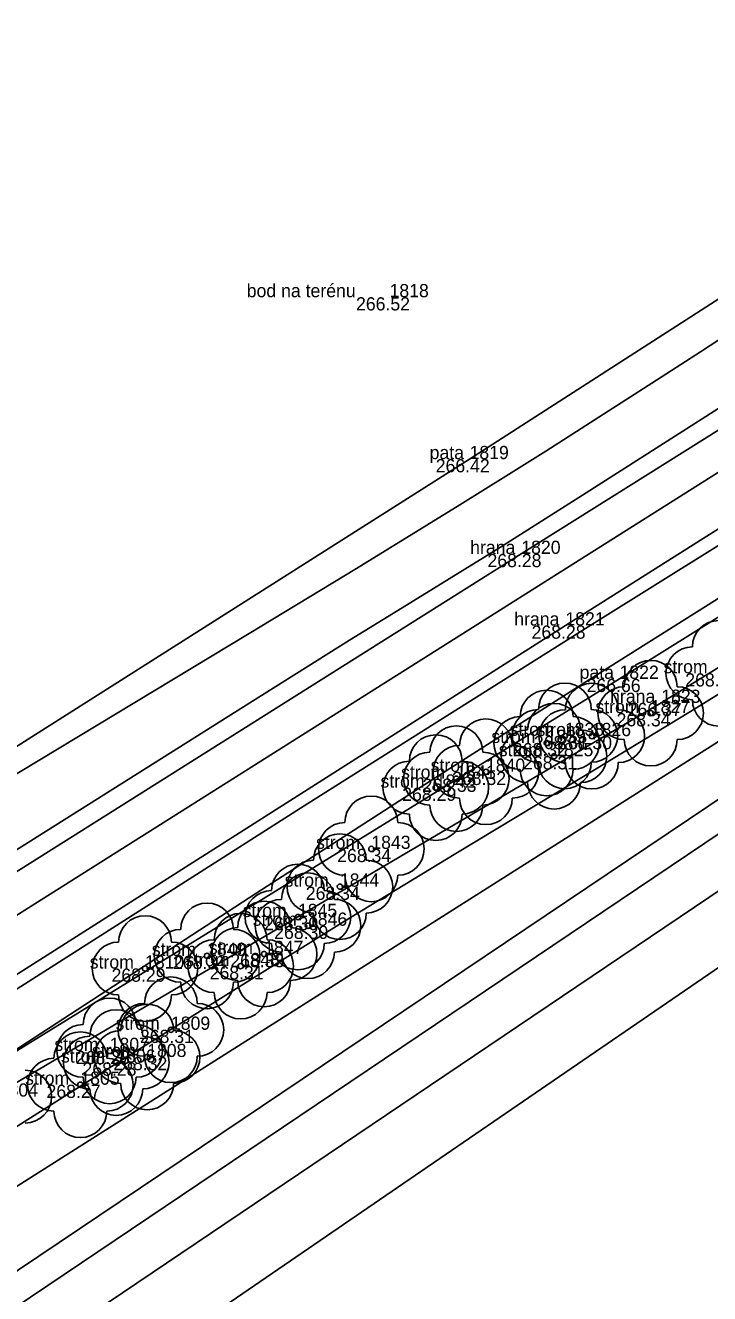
# Model space of a CAD drawing. Extents: x -567962 to -566460, y -1093720 to -1089838.
# Drawn here: x -566832.41 to -566806.5, y -1090168.25 to -1090120.23 of the extents above; entities that cross this region are included whole.
import ezdxf

# ---------------------------------------------------------------- set-up
doc = ezdxf.new("R2010")
doc.units = 0
for name, color, linetype in [('0_osa hráze', 7, 'Continuous'), ('bod_znacka', 7, 'Continuous'), ('cislo_bodu', 7, 'Continuous'), ('Doměření - kraj pole', 7, 'Continuous'), ('hrana_L', 7, 'Continuous'), ('hrana_P', 7, 'Continuous'), ('kod_bodu', 7, 'Continuous'), ('norm_vrst', 7, 'Continuous'), ('stromy', 7, 'Continuous'), ('vyska_bodu', 7, 'Continuous')]:
    doc.layers.add(name, color=color, linetype=linetype)

msp = doc.modelspace()

# ---------------------------------------------------------------- linework, layer by layer
at = {"layer": '0_osa hráze'}
msp.add_lwpolyline([(-566672.431, -1090052.714), (-566840.66, -1090158.92), (-566848.661, -1090164.285)], dxfattribs=at)
at = {"layer": 'bod_znacka'}
for p, q in [((-566818.62, -1090130.52), (-566818.62, -1090130.52)), ((-566815.59, -1090136.65), (-566815.59, -1090136.65)), ((-566813.63, -1090140.24), (-566813.63, -1090140.24)), ((-566811.96, -1090142.95), (-566811.96, -1090142.95)), ((-566809.91, -1090144.97), (-566809.91, -1090144.97)), ((-566808.33, -1090145.88), (-566808.33, -1090145.88)), ((-566808.73, -1090146.27), (-566808.73, -1090146.27)), ((-566812.67, -1090147.4), (-566812.67, -1090147.4)), ((-566811.98, -1090147.13), (-566811.98, -1090147.13)), ((-566810.96, -1090147.14), (-566810.96, -1090147.14)), ((-566812.39, -1090147.9), (-566812.39, -1090147.9)), ((-566816.09, -1090148.75), (-566816.09, -1090148.75)), ((-566814.97, -1090148.49), (-566814.97, -1090148.49)), ((-566816.87, -1090149.09), (-566816.87, -1090149.09)), ((-566819.31, -1090151.41), (-566819.31, -1090151.41)), ((-566820.5, -1090152.84), (-566820.5, -1090152.84)), ((-566822.09, -1090153.99), (-566822.09, -1090153.99)), ((-566821.71, -1090154.32), (-566821.71, -1090154.32)), ((-566825.53, -1090155.46), (-566825.53, -1090155.46)), ((-566823.37, -1090155.39), (-566823.37, -1090155.39)), ((-566827.88, -1090155.94), (-566827.88, -1090155.94)), ((-566824.26, -1090155.85), (-566824.26, -1090155.85)), ((-566826.9, -1090158.26), (-566826.9, -1090158.26)), ((-566829.22, -1090159.06), (-566829.22, -1090159.06)), ((-566827.8, -1090159.29), (-566827.8, -1090159.29)), ((-566828.97, -1090159.5), (-566828.97, -1090159.5)), ((-566830.33, -1090160.34), (-566830.33, -1090160.34))]:
    msp.add_line(p, q, dxfattribs=at)
at = {"layer": 'Doměření - kraj pole'}
msp.add_lwpolyline([(-567047.906, -1090663.012), (-567047.627, -1090662.294), (-567014.86, -1090563.09), (-567002.362, -1090535.532), (-566955.49, -1090317.15), (-566941.63, -1090287.13), (-566940.57, -1090285.53), (-566924.46, -1090259.19), (-566900.35, -1090228.87), (-566877.72, -1090206.37), (-566851.19, -1090186.75), (-566766.44, -1090128.68), (-566717.21, -1090096.34), (-566711.98, -1090092.48)], dxfattribs=at)
at = {"layer": 'hrana_L'}
for p, q in [((-566791.87, -1090121.39), (-566815.59, -1090136.65)), ((-566789.46, -1090125.04), (-566813.63, -1090140.24)), ((-566811.96, -1090142.95), (-566787.81, -1090127.7)), ((-566809.91, -1090144.97), (-566786.12, -1090130.08)), ((-566784.05, -1090130.81), (-566808.33, -1090145.88)), ((-566815.59, -1090136.65), (-566844.61, -1090155.03)), ((-566813.63, -1090140.24), (-566842.64, -1090158.49)), ((-566811.96, -1090142.95), (-566840.71, -1090161.23)), ((-566839.34, -1090163.12), (-566809.91, -1090144.97)), ((-566808.33, -1090145.88), (-566838.78, -1090163.8))]:
    msp.add_line(p, q, dxfattribs=at)
for points in [[(-567053.87, -1090661.84), (-567020.06, -1090563.34), (-567005.258, -1090534.966), (-566958.763, -1090315.674), (-566944.67, -1090284.66), (-566926.49, -1090256.26), (-566902.65, -1090226.03), (-566881.28, -1090203.14), (-566853.44, -1090182.668), (-566715.257, -1090089.634)], [(-567050.54, -1090661.95), (-567017.83, -1090562.99), (-567002.61, -1090535.52), (-566957.72, -1090316.45), (-566942.31, -1090285.07), (-566925.11, -1090257.71), (-566901.37, -1090227.4), (-566879.5, -1090205.23), (-566852.16, -1090184), (-566767.57, -1090126.99), (-566713.28, -1090090.76)], [(-566881.23, -1090201.89), (-566854.215, -1090181.819), (-566730.44, -1090098.63)]]:
    msp.add_lwpolyline(points, dxfattribs=at)
at = {"layer": 'hrana_P'}
msp.add_line((-566838.46, -1090167.8), (-566805.13, -1090146.69), dxfattribs=at)
at = {"layer": 'norm_vrst'}
for points in [[(-566834.345, -1090157.735), (-566821.711, -1090149.692), (-566816.354, -1090146.304), (-566810.753, -1090142.78), (-566801.92, -1090137.275), (-566787.313, -1090128.226), (-566770.443, -1090117.747), (-566767.019, -1090115.602), (-566760.086, -1090111.215), (-566758.405, -1090110.141), (-566751.751, -1090105.855), (-566741.749, -1090099.395), (-566740.082, -1090098.328), (-566733.458, -1090094.138), (-566723.987, -1090088.226), (-566707.595, -1090078.051)], [(-566722.704, -1090081.135), (-566724.539, -1090082.312), (-566725.783, -1090083.096), (-566732.745, -1090087.421), (-566735.695, -1090089.236), (-566737.009, -1090090.068), (-566753.591, -1090100.68), (-566755.229, -1090101.72), (-566761.398, -1090105.6), (-566763.069, -1090106.675), (-566771.123, -1090111.96), (-566784.371, -1090120.618), (-566793.768, -1090126.774), (-566795.254, -1090127.74), (-566801.058, -1090131.472), (-566811.306, -1090138.019), (-566814.423, -1090139.986), (-566818.311, -1090142.378), (-566820.132, -1090143.508), (-566823.816, -1090145.814), (-566841.877, -1090157.194)], [(-566834.812, -1090160.328), (-566823.649, -1090153.068), (-566816.894, -1090148.721), (-566811.051, -1090145.001), (-566804.846, -1090141.096), (-566798.967, -1090137.445), (-566785.889, -1090129.374), (-566780.734, -1090126.153), (-566758.401, -1090112.077), (-566740.288, -1090100.594), (-566732.104, -1090095.458), (-566727.633, -1090092.705), (-566722.521, -1090089.608)], [(-566783.674, -1090117.162), (-566791.52, -1090122.368), (-566799.806, -1090127.931), (-566803.955, -1090130.69), (-566806.841, -1090132.583), (-566808.328, -1090133.547), (-566812.705, -1090136.343), (-566814.213, -1090137.296), (-566815.954, -1090138.383), (-566819.876, -1090140.794), (-566823.933, -1090143.254), (-566834.017, -1090149.319)], [(-566833.079, -1090162.132), (-566828.853, -1090159.464), (-566824.724, -1090156.881), (-566820.322, -1090154.152), (-566816.111, -1090151.584), (-566810.797, -1090148.383), (-566807, -1090146.064), (-566793.395, -1090137.626), (-566790.657, -1090135.906), (-566782.34, -1090130.593), (-566769.314, -1090122.25)]]:
    msp.add_lwpolyline(points, dxfattribs=at)
at = {"layer": 'stromy'}
for centre in [(-566808.73, -1090146.27), (-566812.67, -1090147.4), (-566811.98, -1090147.13), (-566810.96, -1090147.14), (-566812.39, -1090147.9), (-566814.97, -1090148.49), (-566816.09, -1090148.75), (-566816.87, -1090149.09), (-566819.31, -1090151.41), (-566820.5, -1090152.84), (-566822.09, -1090153.99), (-566821.71, -1090154.32), (-566825.53, -1090155.46), (-566823.37, -1090155.39), (-566827.88, -1090155.94), (-566824.26, -1090155.85), (-566826.9, -1090158.26), (-566829.22, -1090159.06), (-566828.97, -1090159.5), (-566827.8, -1090159.29), (-566830.33, -1090160.34)]:
    msp.add_circle(centre, 0.1, dxfattribs=at)
for centre, start, end in [((-566806.15, -1090143.76), 0, 180), ((-566807.15, -1090144.76), 90, 270), ((-566808.73, -1090145.27), 0, 180), ((-566812.67, -1090146.4), 0, 180), ((-566811.98, -1090146.13), 0, 180), ((-566810.96, -1090146.14), 0, 180), ((-566809.73, -1090146.27), 90, 270), ((-566807.73, -1090146.27), 270, 90), ((-566812.39, -1090146.9), 0, 180), ((-566806.15, -1090145.76), 180, 0), ((-566813.67, -1090147.4), 90, 270), ((-566812.98, -1090147.13), 90, 270), ((-566811.96, -1090147.14), 90, 270), ((-566811.67, -1090147.4), 270, 90), ((-566810.98, -1090147.13), 270, 90), ((-566809.96, -1090147.14), 270, 90), ((-566816.09, -1090147.75), 0, 180), ((-566814.97, -1090147.49), 0, 180), ((-566813.39, -1090147.9), 90, 270), ((-566811.39, -1090147.9), 270, 90), ((-566816.87, -1090148.09), 0, 180), ((-566808.73, -1090147.27), 180, 0), ((-566817.09, -1090148.75), 90, 270), ((-566815.97, -1090148.49), 90, 270), ((-566815.09, -1090148.75), 270, 90), ((-566813.97, -1090148.49), 270, 90), ((-566817.87, -1090149.09), 90, 270), ((-566815.87, -1090149.09), 270, 90), ((-566811.98, -1090148.13), 180, 0), ((-566810.96, -1090148.14), 180, 0), ((-566812.67, -1090148.4), 180, 0), ((-566812.39, -1090148.9), 180, 0), ((-566819.31, -1090150.41), 0, 180), ((-566816.09, -1090149.75), 180, 0), ((-566814.97, -1090149.49), 180, 0), ((-566816.87, -1090150.09), 180, 0), ((-566820.31, -1090151.41), 90, 270), ((-566818.31, -1090151.41), 270, 90), ((-566820.5, -1090151.84), 0, 180), ((-566822.09, -1090152.99), 0, 180), ((-566821.5, -1090152.84), 90, 270), ((-566819.5, -1090152.84), 270, 90), ((-566821.71, -1090153.32), 0, 180), ((-566819.31, -1090152.41), 180, 0), ((-566823.09, -1090153.99), 90, 270), ((-566821.09, -1090153.99), 270, 90), ((-566825.53, -1090154.46), 0, 180), ((-566823.37, -1090154.39), 0, 180), ((-566822.71, -1090154.32), 90, 270), ((-566820.71, -1090154.32), 270, 90), ((-566827.88, -1090154.94), 0, 180), ((-566824.26, -1090154.85), 0, 180), ((-566820.5, -1090153.84), 180, 0), ((-566826.53, -1090155.46), 90, 270), ((-566824.37, -1090155.39), 90, 270), ((-566824.53, -1090155.46), 270, 90), ((-566822.37, -1090155.39), 270, 90), ((-566828.88, -1090155.94), 90, 270), ((-566826.88, -1090155.94), 270, 90), ((-566825.26, -1090155.85), 90, 270), ((-566823.26, -1090155.85), 270, 90), ((-566822.09, -1090154.99), 180, 0), ((-566821.71, -1090155.32), 180, 0), ((-566826.9, -1090157.26), 0, 180), ((-566825.53, -1090156.46), 180, 0), ((-566823.37, -1090156.39), 180, 0), ((-566827.88, -1090156.94), 180, 0), ((-566824.26, -1090156.85), 180, 0), ((-566829.22, -1090158.06), 0, 180), ((-566828.97, -1090158.5), 0, 180), ((-566827.9, -1090158.26), 90, 270), ((-566827.8, -1090158.29), 0, 180), ((-566825.9, -1090158.26), 270, 90), ((-566830.33, -1090159.34), 0, 180), ((-566830.22, -1090159.06), 90, 270), ((-566828.8, -1090159.29), 90, 270), ((-566828.22, -1090159.06), 270, 90), ((-566826.8, -1090159.29), 270, 90), ((-566829.97, -1090159.5), 90, 270), ((-566827.97, -1090159.5), 270, 90), ((-566831.33, -1090160.34), 90, 270), ((-566829.33, -1090160.34), 270, 90), ((-566826.9, -1090159.26), 180, 0), ((-566832.42, -1090160.79), 270, 90), ((-566829.22, -1090160.06), 180, 0), ((-566827.8, -1090160.29), 180, 0), ((-566828.97, -1090160.5), 180, 0), ((-566830.33, -1090161.34), 180, 0)]:
    msp.add_arc(centre, 1, start, end, dxfattribs=at)

# ---------------------------------------------------------------- texts
at = {"layer": 'cislo_bodu'}
for s, p in [('1818', (-566818.62, -1090130.52)), ('1819', (-566815.59, -1090136.65)), ('1820', (-566813.63, -1090140.24)), ('1821', (-566811.96, -1090142.95)), ('1822', (-566809.91, -1090144.97)), ('1823', (-566808.33, -1090145.88)), ('1827', (-566808.73, -1090146.27)), ('1839', (-566812.67, -1090147.4)), ('1838', (-566811.98, -1090147.13)), ('1826', (-566810.96, -1090147.14)), ('1825', (-566812.39, -1090147.9)), ('1841', (-566816.09, -1090148.75)), ('1840', (-566814.97, -1090148.49)), ('1842', (-566816.87, -1090149.09)), ('1843', (-566819.31, -1090151.41)), ('1844', (-566820.5, -1090152.84)), ('1845', (-566822.09, -1090153.99)), ('1846', (-566821.71, -1090154.32)), ('1849', (-566825.53, -1090155.46)), ('1847', (-566823.37, -1090155.39)), ('1810', (-566827.88, -1090155.94)), ('1848', (-566824.26, -1090155.85)), ('1809', (-566826.9, -1090158.26)), ('1807', (-566829.22, -1090159.06)), ('1808', (-566827.8, -1090159.29)), ('1806', (-566828.97, -1090159.5)), ('1805', (-566830.33, -1090160.34)), ('1804', (-566833.42, -1090160.79))]:
    msp.add_text(s, height=0.5, dxfattribs=at).set_placement(p)
at = {"layer": 'kod_bodu'}
for s, p in [('bod na terénu', (-566824.029, -1090130.52)), ('pata', (-566817.102, -1090136.65)), ('hrana', (-566815.567, -1090140.24)), ('hrana', (-566813.897, -1090142.95)), ('pata', (-566811.422, -1090144.97)), ('strom', (-566808.244, -1090144.76)), ('hrana', (-566810.267, -1090145.88)), ('strom', (-566810.824, -1090146.27)), ('strom', (-566814.764, -1090147.4)), ('strom', (-566814.074, -1090147.13)), ('strom', (-566813.054, -1090147.14)), ('strom', (-566814.484, -1090147.9)), ('strom', (-566818.184, -1090148.75)), ('strom', (-566817.064, -1090148.49)), ('strom', (-566818.964, -1090149.09)), ('strom', (-566821.404, -1090151.41)), ('strom', (-566822.594, -1090152.84)), ('strom', (-566824.184, -1090153.99)), ('strom', (-566823.804, -1090154.32)), ('strom', (-566827.624, -1090155.46)), ('strom', (-566825.464, -1090155.39)), ('strom', (-566829.974, -1090155.94)), ('strom', (-566826.354, -1090155.85)), ('strom', (-566828.994, -1090158.26)), ('strom', (-566831.314, -1090159.06)), ('strom', (-566829.894, -1090159.29)), ('strom', (-566831.064, -1090159.5)), ('strom', (-566832.424, -1090160.34))]:
    msp.add_text(s, height=0.5, dxfattribs=at).set_placement(p)
at = {"layer": 'vyska_bodu'}
for s, p in [('266.52', (-566819.89, -1090131.02)), ('266.42', (-566816.871, -1090137.15)), ('268.28', (-566814.911, -1090140.74)), ('268.28', (-566813.241, -1090143.45)), ('266.66', (-566811.156, -1090145.47)), ('268.36', (-566807.42, -1090145.26)), ('266.37', (-566809.602, -1090146.38)), ('268.34', (-566810.023, -1090146.77)), ('268.32', (-566813.951, -1090147.9)), ('268.31', (-566813.153, -1090147.63)), ('268.30', (-566812.239, -1090147.64)), ('268.31', (-566813.563, -1090148.4)), ('268.33', (-566817.371, -1090149.25)), ('268.32', (-566816.251, -1090148.99)), ('268.29', (-566818.14, -1090149.59)), ('268.34', (-566820.603, -1090151.91)), ('268.34', (-566821.793, -1090153.34)), ('268.30', (-566823.369, -1090154.49)), ('268.30', (-566822.989, -1090154.82)), ('268.34', (-566826.823, -1090155.96)), ('268.33', (-566824.651, -1090155.89)), ('268.29', (-566829.15, -1090156.44)), ('268.31', (-566825.433, -1090156.35)), ('268.31', (-566828.073, -1090158.76)), ('268.28', (-566830.501, -1090159.56)), ('268.32', (-566829.081, -1090159.79)), ('268.28', (-566830.251, -1090160)), ('268.27', (-566831.613, -1090160.84))]:
    msp.add_text(s, height=0.5, dxfattribs=at).set_placement(p)

doc.saveas('drawing.dxf')
